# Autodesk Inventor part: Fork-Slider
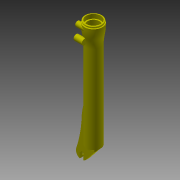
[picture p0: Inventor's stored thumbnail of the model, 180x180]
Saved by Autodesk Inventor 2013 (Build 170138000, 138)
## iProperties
Shininess: 11.0
Length Units: 11272
Angle Units: 11279
Time Units: 11290
Mass Units: 11286
Length Display Precision: 3
Angle Display Precision: 2
Compacted: True
Created: 2001-11
Part Number: Fork-Slider
Document SubType Name: Modeling
Designer: Autodesk, Inc.
Mass: 115.043 g
Surface Area: 625.932 cm^2
Volume: 115.043 cm^3
Density: 1 g/cm^3
Material: Generic
Density: 0.0
Volumn: 0.0
Area: 0.0
PropertySet Name: Model Information
Control State: 0
Master: False
Checked Out: False
Author: Autodesk, Inc.
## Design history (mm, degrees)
node "WorkPlane1"
node "WorkPlane2"
workplane "Work Plane3"
node "WorkPlane3"
sketch "Sketch1"
  geometry: L1 (-491.904, 893.583)-(-489.986, 893.583); L2 (-491.94, 890.889)-(-492.507, 891.195); L3 (-493.987, 888.502)-(-492.544, 888.502); L4 (-493.987, 883.604)-(-493.987, 888.502); L5 (-491.593, 861.235)-(-492.38, 865.605); L6 (-489.986, 628.153)-(-489.986, 843.237); L7 (-477.096, 614.183)-(-489.986, 628.153); L8 (-475.254, 614.183)-(-477.096, 614.183); L9 (-475.254, 630.693)-(-475.254, 614.183); L10 (-486.875, 630.693)-(-475.254, 630.693); L11 (-486.875, 883.423)-(-486.875, 630.693); L12 (-489.986, 883.423)-(-486.875, 883.423); L13 (-489.986, 893.583)-(-489.986, 883.423); L14 (-472.221, 864.964)-(-472.221, 656.569); L15 (-472.221, 864.964)-(-472.221, 656.569); A1 r 1.27 centre (-491.904, 892.313) between (-491.904, 893.583) and (-492.507, 891.195); A2 r 1.27 centre (-492.544, 889.772) between (-492.544, 888.502) and (-491.94, 890.889); A3 r 101.6 centre (-392.387, 883.604) between (-493.987, 883.604) and (-492.38, 865.605); A4 r 101.6 centre (-591.586, 843.237) between (-489.986, 843.237) and (-491.593, 861.235)
  constraints: 30 end point, 8 point on circle, 7 tangent, 6 vertical, 5 horizontal, 4 centre point, 1 collinear, 1 other
revolve "RevolutionFull1" sketch "Sketch1" stored, may be unused: angle "d2" = 360 deg
sketch "Sketch2"
  geometry: L1 (-468.069, 628.153)-(-489.986, 628.153); L2 (-468.069, 735.894)-(-468.069, 628.153); L3 (-450.045, 605.991)-(-450.045, 592.726); L4 (-458.808, 592.726)-(-458.808, 605.991); L5 (-467.317, 599.747)-(-465.345, 597.277); L6 (-489.986, 628.153)-(-467.317, 599.747); A1 r 136.444 centre (-590.87, 676.421) between (-454.426, 676.794) and (-468.069, 735.894); A2 r 273.047 centre (-182.07, 696.209) between (-454.426, 676.794) and (-440.731, 608.748); A3 r 13.97 centre (-454.426, 605.991) between (-450.045, 592.726) and (-440.731, 608.748); A4 r 4.382 centre (-454.426, 605.991) between (-450.045, 605.991) and (-458.808, 605.991); A5 r 13.97 centre (-454.426, 605.991) between (-465.345, 597.277) and (-458.808, 592.726)
  constraints: 12 end point, 10 point on circle, 5 centre point
extrude "ExtrusionBlind1" join sketch "Sketch2" distance "d3" = 9.652; taper "d4" = 0 deg
node "WorkAxis1"
workplane "Work Plane5"
workplane "Work Plane6"
node "WorkPlane4"
workplane "Work Plane8"
node "WorkPlane5"
sketch "Sketch3"
  geometry: L1 (0, -4.165)-(0, 0); L2 (9.652, -4.076)-(9.652, -4.165); L3 (0, -4.165)-(9.652, -4.165); A1 r 17.766 centre (11.43, 13.6) between (0, 0) and (9.652, -4.076)
  constraints: 6 end point, 2 point on circle, 1 centre point
extrude "ExtrusionThru1" cut sketch "Sketch3" stored distance "d17" = 3.302; taper "d18" = 0 deg
sketch "Sketch4"
  geometry: C1 r 14.654 at (14.546, 1.778)
  constraints: 1 centre point
extrude "ExtrusionThru2" cut sketch "Sketch4" stored distance "d19" = 3.302; taper "d20" = 0 deg
sketch "Sketch5"
  geometry: L1 (-458.808, 605.991)-(-458.808, 592.726) reference; L2 (-450.045, 592.726)-(-450.045, 605.991) reference; A1 r 4.382 centre (-454.426, 605.991) between (-450.045, 605.991) and (-458.808, 605.991) reference; A2 r 10.668 centre (-454.426, 605.991) between (-450.045, 596.265) and (-458.808, 596.265)
  constraints: 2 point on circle, 2 point on line, 1 centre point
extrude "ExtrusionBlind2" cut sketch "Sketch5" distance "d21" = 4.572; taper "d22" = 0 deg
sketch "Sketch6"
  geometry: C1 r 6.985 at (-100.202, 21.766)
  constraints: 1 centre point
extrude "ExtrusionBlind3" join sketch "Sketch6" distance "d23" = 20.32; taper "d24" = 0 deg
node "Sketch7"
sketch "Sketch8"
  geometry: L1 (-126.546, 21.766)-(-131.444, 21.766) reference; L2 (-106.924, 19.867)-(-104.178, 19.373) reference; L3 (-108.547, 20.159)-(-106.924, 19.867) reference; L4 (-131.444, 21.766)-(-126.546, 21.766) reference; L5 (-131.444, 20.323)-(-131.444, 21.766) reference; L6 (-134.137, 20.286)-(-133.831, 19.719) reference; L7 (-136.525, 17.766)-(-136.525, 19.683) reference; L8 (-126.365, 17.766)-(-136.525, 17.766) reference; L9 (-126.365, 14.654)-(-126.365, 17.766) reference; L10 (126.365, 14.654)-(-126.365, 14.654) reference; L11 (126.365, 1.587)-(126.365, 14.654) reference; L12 (135.255, 1.587)-(126.365, 1.587) reference; L13 (135.255, 3.034)-(135.255, 1.587) reference; L14 (151.166, 3.034)-(135.255, 3.034) reference; L15 (151.166, 11.43)-(151.166, 3.034) reference; L16 (135.771, 11.43)-(151.166, 11.43) reference; L17 (128.905, 17.766)-(135.771, 11.43) reference; L18 (-86.179, 17.766)-(128.905, 17.766) reference; L19 (-104.178, -19.373)-(-108.547, -20.159) reference; L20 (-126.546, -21.766)-(-131.444, -21.766) reference; L21 (-131.444, -21.766)-(-131.444, -20.323) reference; L22 (-133.831, -19.719)-(-134.137, -20.286) reference; L23 (-136.525, -19.683)-(-136.525, -17.766) reference; L24 (-136.525, -17.766)-(-126.365, -17.766) reference; L25 (-126.365, -17.766)-(-126.365, -14.654) reference; L26 (-126.365, -14.654)-(126.365, -14.654) reference; L27 (126.365, -14.654)-(126.365, -1.587) reference; L28 (126.365, -1.587)-(135.255, -1.587) reference; L29 (135.255, -1.587)-(135.255, -3.034) reference; L30 (135.255, -3.034)-(142.875, -3.034) reference; L31 (142.875, -3.034)-(142.875, -4.875) reference; L32 (142.875, -4.875)-(128.905, -17.766) reference; L33 (128.905, -17.766)-(-86.179, -17.766) reference; C1 r 6.35 at (-124.333, 15.39); A1 r 6.985 centre (-100.202, 21.766) between (-94.264, 18.088) and (-106.924, 19.867) reference; A2 r 101.6 centre (-86.179, 119.366) between (-104.178, 19.373) and (-94.264, 18.088) reference; A3 r 101.6 centre (-126.546, -79.834) between (-108.547, 20.159) and (-123.263, 21.713) reference; A4 r 101.6 centre (-126.546, -79.834) between (-125.109, 21.756) and (-126.546, 21.766) reference; A5 r 1.27 centre (-132.714, 20.323) between (-133.831, 19.719) and (-131.444, 20.323) reference; A6 r 1.27 centre (-135.255, 19.683) between (-134.137, 20.286) and (-136.525, 19.683) reference; A7 r 101.6 centre (-86.179, 119.366) between (-94.264, 18.088) and (-86.179, 17.766) reference; A8 r 101.6 centre (-126.546, -79.834) between (-123.263, 21.713) and (-125.109, 21.756) reference; A9 r 101.6 centre (-86.179, -119.366) between (-86.179, -17.766) and (-104.178, -19.373) reference; A10 r 101.6 centre (-126.546, 79.834) between (-126.546, -21.766) and (-108.547, -20.159) reference; A11 r 1.27 centre (-132.714, -20.323) between (-131.444, -20.323) and (-133.831, -19.719) reference; A12 r 1.27 centre (-135.255, -19.683) between (-136.525, -19.683) and (-134.137, -20.286) reference
  constraints: 1 centre point, 1 tangent
extrude "ExtrusionBlind4" join sketch "Sketch8" distance "d26" = 23.368; taper "d27" = 0 deg
node "Sketch9"
extrude "ExtrusionToPlane1" cut stored distance "d29" = 3.302; taper "d30" = 0 deg
  node "Sketch10"
extrude "ExtrusionBlind5" cut distance "d31" = 50.8; taper "d32" = 0 deg
  node "Sketch11"
workplane "Work Plane10"
sketch "Sketch13"
  geometry: C1 r 3.034 at (0, 0); A1 r 3.034 centre (0, 0) between (-2.458, 1.778) and (2.458, 1.778) reference
  constraints: 1 centre point, 1 coincident, 1 concentric
workplane "Work Plane11"
extrude "Extrusion9" join sketch "Sketch13" stored distance "d34" = 25.4; taper "d35" = 0 deg
sketch "Sketch14"
  geometry: L1 (-2.458, 1.778)-(2.458, 1.778) reference; C1 r 3.034 at (0, 0); A1 r 3.034 centre (0, 0) between (-2.458, 1.778) and (2.458, 1.778) reference
  constraints: 1 centre point, 1 coincident, 1 concentric
extrude "Extrusion10" cut sketch "Sketch14" stored distance "d36" = 25.4; taper "d37" = 0 deg
sketch "Sketch15"
  geometry: C1 r 3.034 at (0, 0) reference
hole "Hole1" sketch "Sketch15" at (0, 0) diameter "d38" = 3.175; stored, may be unused: countersink angle "d42" = 82 deg, drill point angle "d44" = 118 deg; dims "d39" = 12.7, "d40" = 9.525, "d41" = 6.35, "d43" = 19.05
sketch "Sketch16"
  geometry: C1 r 6.985 at (0, 0) reference
hole "Hole2" sketch "Sketch16" at (0, 0) diameter "d45" = 4.3434; stored, may be unused: countersink angle "d49" = 82 deg, drill point angle "d51" = 118 deg; dims "d46" = 12.7, "d47" = 9.525, "d48" = 6.35, "d50" = 12.7
sketch "Sketch17"
  geometry: C1 r 6.35 at (0, 0) reference
hole "Hole3" sketch "Sketch17" at (0, 0) diameter "d52" = 3.2512; stored, may be unused: countersink angle "d56" = 82 deg, drill point angle "d58" = 118 deg; dims "d53" = 12.7, "d54" = 9.525, "d55" = 6.35, "d57" = 12.7
body "Solid1"
other parameters: "d0" = -11.43, "d1" = -19.05, "d5" = 0, "d6" = 0, "d7" = 0, "d8" = 0, "d9" = 0, "d10" = 0, "d11" = 0, "d12" = 0, "d13" = 0, "d14" = 0, "d15" = 0, "d16" = 0, "d25" = 0, "d28" = 0, "d33" = -7.62
